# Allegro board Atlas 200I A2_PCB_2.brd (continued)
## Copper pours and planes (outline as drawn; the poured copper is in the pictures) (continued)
V_STBY_3V3 on TOP (solid shape): 21.39,117.73 21.39,117.02 21.31,116.94 20.32,116.94 20.19,117.07 20.19,117.22 21.16,117.22 21.16,117.58 20.73,117.58 20.73,117.22 20.19,117.22 20.19,117.6 20.37,117.78 21.34,117.78
V_STBY_3V3 on TOP (solid shape): 155.58,63.22 155.58,62.88 155.4,62.88 155.4,62.15 154.94,61.7 154.28,61.7 154.18,61.8 154.18,61.98 154.86,61.98 154.86,62.38 154.46,62.38 154.46,61.98 154.18,61.98 154.18,62.59 155.07,63.47 155.32,63.47
V_STBY_3V3 on TOP (solid shape): 59.51,33.48 59.51,30.3 59.21,30 59.21,28.47 58.8,28.07 57.15,28.07 57.02,28.19 57.02,28.32 57.28,28.32 57.28,28.96 58.67,30.35 58.67,30.78 59.28,30.78 59.28,31.65 58.98,31.65 58.98,30.78 58.67,30.78 58.67,33.48 58.8,33.6 59.39,33.6
V_STBY_3V3 on TOP (solid shape): 164.26,45.97 164.26,44.42 164.21,44.37 162.66,44.37 162.64,44.4 162.64,44.6 164.14,44.6 164.14,45.03 163.91,45.03 163.91,44.6 163.12,44.6 163.12,45.03 162.89,45.03 162.89,44.6 162.64,44.6 162.64,45.59 162.76,45.72 163.47,45.72 163.55,45.8 163.55,46.43 163.8,46.43
V_STBY_3V3 on TOP (solid shape): 186.79,160.15 186.79,157.96 186.51,157.68 184.96,157.68 184.79,157.86 184.79,158.8 185.6,158.8 185.6,159.13 185.14,159.13 185.14,158.8 184.79,158.8 184.79,159.77 185.6,159.77 185.6,160.07 185.19,160.07 185.19,159.77 184.79,159.77 184.79,160.15 184.91,160.27 186.66,160.27
V_STBY_3V3 on TOP (solid shape): 164.67,35.94 164.67,35.33 164.64,35.31 162.13,35.31 162.05,35.38 162.05,35.41 164.52,35.41 164.52,35.81 163.3,35.81 163.3,35.41 162.05,35.41 162.05,35.58 162.48,35.58 162.48,36.04 162.23,36.04 162.23,35.58 162.05,35.58 162.05,36.27 162.2,36.42 163.09,36.42 163.2,36.52 163.2,37.16 163.45,37.16
V_STBY_3V3 on TOP (solid shape): 198.15,62.26 198.17,61.79 198.25,61.34 198.25,59.28 198.07,59.11 198.07,58.6 197.92,58.45 197.66,58.45 197.66,58.67 196.98,58.67 196.98,58.52 197.03,58.52 197.03,58.39 196.8,58.39 196.77,58.42 196.77,58.83 196.88,58.93 197.16,58.93 197.59,59.36 197.59,70.18 198.15,70.18
V_STBY_3V3 on TOP (solid shape): 87,147.24 86.97,147.22 86.64,147.22 86.36,146.94 86.11,146.94 85.98,147.07 85.98,147.45 86.79,147.45 86.79,147.73 86.44,147.73 86.44,147.45 85.98,147.45 85.98,147.73 85.73,147.98 85.22,147.98 85.17,148.03 85.17,148.23 85.24,148.31 86.77,148.31 86.77,148.61 86.44,148.61 86.44,148.31 85.24,148.31 85.7,148.77 87,148.77
V_STBY_3V3 on TOP (solid shape): 203.63,26.76 203.63,25.22 203.53,25.12 202.69,25.12 202.55,25.26 202.53,25.28 202.49,25.31 202.43,25.33 202.43,25.35 203.38,25.35 203.38,25.63 202.97,25.63 202.97,25.35 202.43,25.35 202.43,25.55 202.36,25.55 202.26,25.65 200.58,25.65 200.48,25.76 200.48,26.29 203.35,26.29 203.35,26.57 202.92,26.57 202.92,26.29 200.48,26.29 200.48,26.49 200.54,26.55 202.12,26.55 202.13,26.54 202.46,26.54 202.7,26.79 203.6,26.79
V_STBY_3V3 on TOP (solid shape): 134.91,14.25 134.91,11.56 134.38,11.03 134.38,8.54 134.22,8.38 134.22,7.65 133.84,7.27 132.9,7.27 132.75,7.42 132.75,7.93 132.52,8.16 132.12,8.16 131.94,8.33 131.94,8.36 132.75,8.36 132.75,8.69 132.24,8.69 132.24,8.36 131.94,8.36 131.94,9.76 132.62,10.44 134.15,10.44 134.15,10.75 133.64,10.75 133.64,10.44 132.62,10.44 133.72,11.53 134.02,11.53 134.38,11.89 134.38,13.44 134.02,13.79 132.85,13.79 132.75,13.9 132.75,14.58 133.01,14.84 134.33,14.84
V_STBY_3V3 on TOP (solid shape): 158.25,60.06 158.25,59.45 158.29,59.41 158.29,58.19 158.57,57.91 158.57,57.2 158.47,57.1 158.24,57.1 158.24,57.91 157.99,57.91 157.99,57.1 157.61,57.1 157.61,58.04 157.23,58.04 157.23,57.1 156.95,57.1 156.79,57.25 156.79,58.27 158.04,58.27 158.04,58.7 157.76,58.7 157.76,58.27 156.79,58.27 156.79,58.39 156.67,58.52 157.45,58.52 157.45,58.83 157,58.83 157,58.52 156.67,58.52 156.62,58.57 156.62,58.98 156.9,59.26 157.01,59.26 157.1,59.35 157.1,59.63 157.66,60.2 158.12,60.2
V_STBY_3V3 on TOP (solid shape): 24.59,53.59 24.59,53.01 24.97,52.63 24.97,52.02 24.94,51.99 24.74,51.99 24.64,51.89 24.59,51.89 24.59,51.84 24.51,51.76 24.51,51.54 24.49,51.51 23.8,51.51 23.75,51.46 23.75,51.31 23.83,51.23 24.49,51.23 24.51,51.21 24.51,51.03 24.49,51 23.7,51 23.44,51.26 23.44,52.43 23.29,52.58 19.05,52.58 18.73,52.26 18.73,51.75 17.02,50.04 15.37,50.04 15.11,50.29 15.11,51.69 15.37,51.94 17.53,51.94 17.65,52.07 17.65,52.96 17.78,53.09 24.26,53.09 24.26,53.52 23.75,53.52 23.75,53.09 17.78,53.09 18.42,53.72 18.52,53.72 18.54,53.75 24.44,53.75
V_STBY_3V3 on TOP (solid shape): 82.45,165.3 82.45,163.85 82.58,163.73 82.58,162.53 82.45,162.41 81.74,162.41 81.53,162.2 81.53,161.8 80.87,161.14 80.62,161.14 80.26,160.78 80.26,159.13 80.26,159.13 79.63,159.13 79.63,159.13 79.63,160.91 80.39,161.67 80.39,161.72 81.03,161.72 81.03,161.98 80.62,161.98 80.62,161.72 80.39,161.72 80.39,162.56 82.19,162.56 82.19,162.79 81.84,162.79 81.84,162.56 80.39,162.56 80.39,162.61 81.03,162.61 81.03,162.89 80.57,162.89 80.57,162.61 80.39,162.61 80.39,162.94 80.37,162.94 80.01,163.3 80.01,163.42 82.35,163.42 82.35,163.65 81.97,163.65 81.97,163.42 80.01,163.42 80.01,164.59 80.95,165.53 82.22,165.53
V_STBY_3V3 on TOP (solid shape): 165.07,69.29 165.07,69.29 166.46,69.29 166.64,69.11 166.64,68.2 166.21,67.77 166.21,66.55 166.16,66.5 165.86,66.5 165.86,67.31 165.61,67.31 165.61,67.18 165.48,67.18 165.48,67.18 165.26,67.18 165.26,67.03 165.56,67.03 165.56,67.06 165.61,67.06 165.61,66.31 165.27,65.97 165.27,65.97 165.14,65.84 165.14,65.43 164.31,65.43 164.31,65.07 165.14,65.07 165.14,64.8 164.2,64.8 163.77,65.23 163.77,65.76 163.47,66.07 158.31,66.07 158.3,66.08 164.61,66.08 164.61,66.38 164.46,66.38 164.46,66.08 158.3,66.08 157.73,66.64 157.73,68.55 166.5,68.55 166.5,68.96 166.19,68.96 166.19,68.55 165.61,68.55 165.61,68.96 165.35,68.96 165.35,68.55 157.73,68.55 157.73,69.21 157.94,69.42 164.94,69.42
V_STBY_3V3 on TOP (solid shape): 121.18,27.71 121.18,27.23 121.11,27.15 118.75,27.15 118.52,27.38 119.89,27.38 119.89,27.76 119.46,27.76 119.46,27.38 118.52,27.38 118.49,27.41 117.86,27.41 115.27,24.82 114.35,24.82 113.34,23.8 113.13,23.8 113.13,19.63 113.77,19 115.14,19 115.85,18.29 115.85,16.33 115.72,16.2 112.45,16.2 111.68,16.97 111.68,23.9 111.94,24.15 111.94,26.59 113.64,28.3 115.28,28.3 115.29,28.29 115.32,28.29 115.34,28.27 115.36,28.25 115.37,28.22 115.38,28.2 115.38,28.17 115.36,28.13 115.35,28.08 115.34,28.03 115.34,27.97 115.35,27.92 115.36,27.87 115.38,27.82 115.41,27.77 115.45,27.73 115.49,27.7 115.54,27.67 115.59,27.64 115.64,27.63 115.69,27.62 115.75,27.62 115.8,27.63 115.85,27.64 115.9,27.67 115.95,27.7 115.99,27.73 116.03,27.77 116.06,27.82 116.08,27.87 116.08,27.89 120.29,27.89 120.29,28.19 119.74,28.19 119.74,27.89 116.08,27.89 116.09,27.92 116.1,27.97 116.1,28.03 116.09,28.09 116.08,28.14 116.05,28.19 116.03,28.23 116.03,28.3 116.08,28.3 116.1,28.32 119.79,28.32 119.88,28.42 120.47,28.42
V_STBY_3V3 on TOP (solid shape): outline of 134 points within 66.8,147.95 79.12,163.3
V_STBY_3V3 on TOP (solid shape): outline of 191 points within 171.58,36.27 175.51,53.59
V_STBY_3V3 on BOTTOM (solid shape): outline of 106 points within 113.11,7.24 134.32,17.78
V_STBY_3V3 on BOTTOM (solid shape): 184.9,16.72 184.88,16.65 184.87,16.57 185,16.27 185.31,16.14 185.38,16.15 185.46,16.17 193.68,7.95 195.58,7.95 199.72,12.09 199.77,12.04 210.31,12.04 210.59,12.32 211.58,12.32 211.96,11.94 211.96,11.25 211.4,10.69 202.31,10.69 202.39,10.82 202.41,10.97 201.98,11.4 201.55,10.97 201.58,10.82 201.65,10.69 201.6,10.69 195.55,4.65 190.4,4.65 189.81,5.23 189.81,8.69 181.34,17.16 181.61,17.3 181.73,17.59 181.6,17.89 181.29,18.02 181.01,17.91 180.86,17.64 180.34,18.16 179.38,18.16 179.32,18.11 178.97,18.11 178.92,18.16 171.22,18.16 171.04,18.34 171.04,19.13 171.2,19.28 182.35,19.28
V_STBY_3V3 on BOTTOM (solid shape): outline of 562 points within 39.91,20.6 60.1,33.83
V_STBY_3V3 on BOTTOM (solid shape): outline of 709 points within 149.5,44.91 165.99,65.13
V_STBY_3V3 on BOTTOM (solid shape): outline of 1075 points within 26.09,159.36 82.7,169.8
V_STBY_3V3 on ART03 (solid shape): outline of 148 points within 163.7,26.77 180.05,32.77
V_STBY_3V3 on ART03 (solid shape): outline of 188 points within 69.09,152.15 90.3,154.69
V_STBY_3V3 on ART03 (solid shape): outline of 935 points within 19.15,136.95 38.18,161.26
V_STBY_3V3 on ART04 (solid shape): 21.08,117.5 21.08,116.81 21.01,116.74 20.2,116.74 20,116.53 19.56,116.53 18.44,115.42 16.69,115.42 16.51,115.59 16.51,116.46 17.92,117.87 20.71,117.87
V_STBY_3V3 on ART04 (solid shape): outline of 300 points within 39.49,19.66 46.99,28.83
V_STBY_3V3 on ART04 (solid shape): outline of 347 points within 8.76,137.16 21.46,146.18
V_STBY_3V3 on ART04 (solid shape): outline of 567 points within 191.01,20.86 208.41,43.43
V_STBY_3V3 on ART04 (solid shape): outline of 932 points within 80.7,164.85 117.53,192.99
V_STBY_3V3 on TOP: 16.03,116.23 17.98,116.23 18.14,116.08 18.14,115.37 16.79,114.02 15.16,114.02 13.84,112.7 10.24,112.7 9.63,112.09 4.75,112.09 4.62,112.22 4.62,115.49 4.75,115.62 5.39,115.62 5.49,115.52 5.49,114.88 5.82,114.55 5.82,114.1 6.78,113.13 9.07,113.13 9.5,113.56 9.5,115.32 9.63,115.44 10.08,115.44 10.26,115.26 10.26,114.3 10.8,113.77 12.88,113.77 13.61,114.5 14.12,114.5 14.61,114.99 15.7,114.99 15.93,115.21 15.93,116.13 ; 4 cut-outs
V_STBY_3V3 on TOP: 40.64,20.7 40.64,22.86 40.77,22.99 41.53,22.99 41.66,22.86 41.66,22.2 41.53,22.07 41.53,21.18 41.66,21.06 41.66,20.7 41.53,20.57 40.77,20.57 ; 1 cut-out
V_STBY_3V3 on TOP: 8.38,139.12 9.7,139.12 9.98,138.84 9.98,138.07 9.83,137.92 8.51,137.92 8.18,138.25 8.18,138.91 ; 1 cut-out
V_STBY_3V3 on TOP: 20.37,137.34 21.39,137.34 21.51,137.46 21.51,138.68 21.39,138.81 19.79,138.81 19.74,138.76 19.74,138.38 20.24,137.87 20.24,137.46 ; 2 cut-outs
V_STBY_3V3 on TOP: 204.98,30.68 205.54,30.68 205.59,30.63 205.59,28.8 205.92,28.47 206.12,28.47 206.53,28.07 206.53,25.83 206.38,25.68 205.54,25.68 205.33,25.88 205.33,27.08 204.7,27.71 204.7,28.12 204.67,28.14 204.67,28.5 204.5,28.68 201.96,28.68 201.3,28.02 200.58,28.02 200.41,28.19 200.41,29.26 201.07,29.92 202.06,29.92 202.74,30.61 204.9,30.61 ; 3 cut-outs
V_STBY_3V3 on TOP: 32.64,161.8 36.32,161.8 36.86,161.26 36.86,160.38 36.65,160.17 35.59,160.17 35.43,160.32 35.43,160.58 34.98,161.04 32.64,161.04 32.51,161.16 32.51,161.67 ; 2 cut-outs
V_STBY_3V3 on BOTTOM: 122.43,175.28 122.43,185.57 118.69,189.31 115.65,189.31 115.21,188.87 115.21,187.6 115.75,187.07 118.06,187.07 119.15,185.98 119.15,174.55 119.13,174.52 119.13,172.36 120.47,171.02 137.64,171.02 139.7,168.96 185.47,168.96 188.95,172.44 188.95,172.92 190.88,174.85 194.92,174.85 198.17,171.6 198.17,168.93 201.02,166.09 202.16,166.09 202.46,166.39 202.46,167.69 200.84,169.32 200.84,174.5 198.09,177.24 187.45,177.24 182.75,172.54 139.5,172.54 138.25,173.79 123.93,173.79
V_STBY_3V3 on BOTTOM: 86.36,153.67 89.79,153.67 89.92,153.54 89.92,152.65 88.34,151.08 88.34,150.17 86.87,148.7 86.87,147.12 86.46,146.71 85.75,146.71 85.32,147.14 85.32,149.96 86.11,150.75 86.11,153.42
V_STBY_3V3 on BOTTOM: outline of 312 points within 185.55,38.97 213.87,52.41
V_STBY_3V3 on ART03: 185.29,41.22 187.96,41.22 187.96,39.6 182.06,39.6 181.31,40.35 181.31,40.77 181.74,41.2 185.27,41.2
V_STBY_3V3 on ART03: 148.78,63.02 150,63.02 150.38,62.64 150.38,61.51 149.91,61.05 142.16,61.05 141.01,62.21 141.01,62.61 143.31,62.61 143.31,62.43 148.2,62.43
V_STBY_3V3 on ART03: outline of 131 points within 4.24,3.7 176.48,139.83
V_STBY_3V3 on ART03: 155.32,69.75 157.99,69.75 158.55,69.19 158.55,59.38 158.24,59.08 157.15,59.08 157.02,59.21 157.02,59.71 154.36,62.38 154.36,68.78
V_STBY_3V3 on ART04: 120.7,27.61 121.08,27.61 121.72,26.97 126.44,26.97 126.44,26.19 127.33,26.19 127.33,25.98 127.97,25.98 128.12,25.83 128.12,25.48 127.51,24.87 127.51,24.13 126.11,24.13 126.06,24.18 126.06,24.61 126.01,24.61 125.02,25.6 121.54,25.6 120.93,26.21 120.93,26.31 120.32,26.92 120.32,27.23
V_STBY_3V3 on ART04: 165.66,38.35 164.52,39.5 164.52,45.9 164.31,46.1 162.76,46.1 162.43,45.77 162.43,36.25 161.06,34.87 161.06,26.8 169.55,18.31 171.12,18.31 171.12,18.29 176,18.29 176.23,18.52 176.23,19.48 175.46,20.24 172.75,20.24 172.58,20.41 172.58,23.08 170.59,25.07 170.59,25.55 166.7,29.44 166.7,30.56 165.66,31.6
V_STBY_3V3 on ART04: 178.68,40.88 182.16,40.88 182.85,40.2 182.85,35.27 179.72,32.15 178.67,32.15 178.56,32.26 178.44,32.13 173.91,32.13 173.91,35.05 173.2,35.05 172.39,35.86 172.39,38.2 172.54,38.35 172.54,38.68 174.3,40.44 177.29,40.44 177.52,40.21 178,40.21
V_STBY_5V0 on TOP (solid shape): 238,179.25 238,178.13 237.69,177.82 236.93,177.82 236.91,177.8 236.35,177.8 236.09,177.55 236.09,176.78 234.57,176.78 234.32,177.04 234.32,178.94 234.57,179.2 235.41,179.2 235.59,179.37 237.87,179.37
V_STBY_5V0 on TOP (solid shape): 155.41,60.67 155.41,59.85 155.7,59.56 155.7,58.42 155.58,58.29 155.24,58.29 155.24,58.32 154.66,58.32 154.18,58.8 154.18,60.58 154.66,60.58 154.66,60.96 154.43,60.96 154.43,60.58 154.18,60.58 154.18,61.21 154.2,61.24 154.84,61.24
V_STBY_5V0 on TOP (solid shape): 138.18,24.87 139.07,24.87 139.12,24.82 139.12,23.82 138.91,23.62 138.49,23.62 138.42,23.64 138.35,23.65 138.1,23.55 137.98,23.32 137.87,23.22 136.04,23.22 135.48,23.77 135.48,25.12 135.5,25.13 137.91,25.13
V_STBY_5V0 on TOP (solid shape): 98.27,158.06 98.27,154.1 97.03,152.86 97.03,149.1 96.34,148.41 96.34,145.52 95.86,145.03 94.21,145.03 94.01,145.24 94.01,145.41 94.77,145.41 94.77,145.69 94.21,145.69 94.21,145.41 94.01,145.41 94.01,146.28 94.77,146.28 94.77,146.58 94.29,146.58 94.29,146.28 94.01,146.28 94.01,147.6 94.21,147.8 94.21,153.49 95.25,154.53 95.25,158.19 95.48,158.42 97.92,158.42
V_STBY_5V0 on TOP (solid shape): 151.41,30.63 151.41,30.48 151.59,30.3 152.22,30.3 152.22,30.02 152.12,29.92 151.59,29.92 150.72,29.06 150.72,28.57 150.27,28.12 150.27,27.01 150.24,26.99 150.19,26.95 150.15,26.91 150.12,26.85 150.09,26.8 150.07,26.74 150.06,26.68 150.06,26.62 150.07,26.57 150.08,26.52 150.09,26.49 150.07,26.47 150.02,26.43 149.99,26.37 149.96,26.32 149.95,26.26 149.94,26.19 149.94,26.14 149.94,26.08 149.95,26.03 149.96,26.01 149.86,25.91 148.08,25.91 147.96,26.03 147.96,29.97 150.88,29.97 150.88,30.61 150.5,30.61 150.5,29.97 147.96,29.97 147.96,30.58 148.29,30.91 151.13,30.91
V_STBY_5V0 on TOP (solid shape): 187.05,38.43 187.05,36.63 186.36,35.94 186.36,35.48 186.06,35.18 185.42,35.18 185.42,35.13 184.2,35.13 183.39,35.94 184.02,35.94 184.03,35.88 184.04,35.83 184.06,35.78 184.09,35.73 184.12,35.69 184.16,35.65 184.21,35.61 184.25,35.59 184.31,35.57 184.36,35.56 184.42,35.56 184.47,35.56 184.53,35.58 184.58,35.6 184.63,35.63 184.67,35.67 184.71,35.71 184.74,35.75 184.76,35.8 184.78,35.86 184.79,35.91 184.79,35.97 184.78,36.02 184.76,36.08 184.74,36.13 184.71,36.17 184.67,36.22 184.63,36.25 184.58,36.28 184.53,36.3 184.47,36.32 184.42,36.32 184.36,36.32 184.31,36.31 184.25,36.29 184.21,36.27 184.16,36.23 184.12,36.2 184.09,36.15 184.06,36.1 184.04,36.05 184.03,36 184.02,35.94 183.39,35.94 183.34,35.99 183.34,37.97 184.02,38.66 186.82,38.66
V_STBY_5V0 on BOTTOM (solid shape): 34.49,168.27 34.54,168.27 34.8,168.02 34.8,167.89 34.82,167.87 46.08,167.87 46.46,167.49 46.46,166.25 46.46,166.25 46.46,164.87 46.13,164.54 42.24,164.54 40.14,166.65 34,166.65 33.07,167.58 32.48,168.17 32.48,168.66 32.82,168.99 33.78,168.99
V_STBY_5V0 on BOTTOM (solid shape): outline of 196 points within 28.8,23.37 77.6,51.68
V_STBY_5V0 on BOTTOM (solid shape): outline of 372 points within 94.11,145.92 98.79,173.14
V_STBY_5V0 on ART03 (solid shape): outline of 4971 points within 10.24,49.25 34.82,170.97
V_STBY_5V0 on TOP: 192.38,24.76 192.38,23.49 192.61,23.27 194.08,23.27 194.59,23.77 194.59,24.54 194.41,24.71 193.93,24.71 193.65,24.99 193.65,25.65 193.45,25.86 191.77,25.86 191.72,25.81 191.72,25.3 191.77,25.25 191.9,25.25 ; 1 cut-out
V_STBY_5V0 on TOP: 105.18,192.18 104.52,191.52 104.52,187.96 104.78,187.71 105.92,187.71 106.55,188.34 106.55,192 106.38,192.18
V_STBY_5V0 on TOP: 126.24,191.77 124.71,191.77 124.08,191.13 124.08,189.23 124.84,188.47 126.11,188.47 126.37,188.72 126.37,191.64
V_STBY_5V0 on ART03: outline of 179 points within 43.08,163.7 235.71,190.94
V_STBY_5V0 on ART03: 183.54,36.55 186.61,36.55 186.7,36.46 187.06,36.46 187.96,35.56 187.96,33.45 188.6,32.82 190.88,32.82 191.29,32.41 191.29,30.78 190.96,30.45 184.63,30.45 184.56,30.53 183.41,30.53 181.25,32.69 170.92,32.69 170.61,32.38 170.61,31.83 169.72,30.94 166.52,30.94 155.52,19.94 136.45,19.94 135.38,21.01 135.38,22.81 136.32,23.75 145.49,23.75 148.21,26.47 157.71,26.47 165.79,34.54 171.15,34.54 172.03,35.43 176.53,35.43 176.78,35.18 181.48,35.18 182.75,36.45 182.75,36.55 183.54,36.55
V_STBY_5V0 on ART04: 155.14,59.56 156.72,59.56 157.91,58.37 157.91,54.51 158.75,53.67 158.75,51.21 159.7,50.25 159.7,29.45 155.45,25.2 148.06,25.2 147.83,25.42 147.83,27.15 147.98,27.3 147.98,28.68 148.54,29.23 149.73,29.23 150.39,29.9 156.13,29.9 156.85,30.61 156.85,32.64 156.39,33.1 156.39,42.47 154.97,43.89 154.97,45.57 155.04,45.64 155.04,50.06 154.51,50.6 154.51,58.93 ; 3 cut-outs
V_STBY_5V0 on ART04: 189.74,27.3 189.74,30.86 190.32,31.44 191.03,31.44 191.24,31.24 191.24,28.9 193.47,26.67 193.47,25.2 193.29,25.02 192.02,25.02
V_STBY_5V0 on ART04: 128.3,25.09 136.88,25.25 138.02,24.1 138.02,23.19 137.72,22.88 134.32,22.88 134.32,22.81 132.56,21.06 128.91,21.06 128.09,21.87 79.88,21.87 79.6,22.15 79.12,22.15 78.87,22.4 77.34,22.4 76.45,23.29 76.45,24.97 76.73,25.25 124.92,25.2 125.37,24.79 125.5,24.66 125.7,24.36 127.66,24.36 127.86,24.64 128.02,24.79
V_STBY_12V0 on TOP (solid shape): 188.04,73.23 188.04,71.55 187.71,71.22 186.08,71.22 185.93,71.37 185.93,73.51 186.06,73.63 187.64,73.63
V_STBY_12V0 on TOP (solid shape): 33.25,156.46 33.25,152.79 29.92,152.79 29.79,152.92 29.79,156.54 29.95,156.69 33.02,156.69
V_STBY_12V0 on TOP (solid shape): 105.21,183.41 105.21,181.46 104.98,181.23 104.37,181.23 104.09,180.95 104.09,180.48 104.01,180.41 104.01,179.3 103.84,179.12 103.81,179.12 103.71,179.02 103.71,178.49 103.45,178.49 103.45,178.23 103.71,178.23 103.71,178.08 103.61,177.98 103.61,177.11 103.58,177.09 103.2,177.09 103.07,177.22 103.07,177.77 102.93,177.91 102.93,178.62 102.18,179.37 101.07,179.37 101.07,183.24 101.32,183.49 105.13,183.49
V_STBY_12V0 on TOP (solid shape): 102.41,169.75 102.41,167.59 102.11,167.28 102.11,165.73 102.18,165.66 102.18,164.79 102.29,164.69 102.29,163.88 102.26,163.85 102.06,163.85 102.06,164.49 101.75,164.49 101.75,163.85 101.57,163.85 101.57,164.52 101.27,164.52 101.27,163.85 100.78,163.85 100.78,163.86 100.33,163.86 100.17,164.02 100.17,165.02 100.15,165.03 100.15,165.07 101.85,165.07 101.85,165.35 101.42,165.35 101.42,165.07 100.15,165.07 100.15,165.38 99.92,165.61 99.92,167.31 99.29,167.94 98.48,167.94 98.22,168.2 98.22,169.72 98.65,170.15 102.01,170.15
V_STBY_12V0 on TOP (solid shape): 168.73,63.63 167.16,63.63 166.22,62.48 166.22,60.75 166.22,59.5 166.65,59.07 166.65,58.28 166.68,58.25 166.68,57.99 166.85,57.81 166.85,57.76 167.39,57.76 167.41,57.78 169.49,57.78 169.49,57.75 169.7,57.75 169.93,57.53 169.93,56.31 169.6,55.98 166.37,55.98 165.28,57.07 159.82,57.07 159.54,57.35 159.54,57.61 159.57,57.65 159.6,57.71 159.63,57.78 159.65,57.85 159.66,57.92 159.67,58 159.66,58.07 159.65,58.14 159.63,58.21 159.6,58.28 159.56,58.34 159.54,58.37 159.54,58.62 166.47,58.62 166.47,58.9 165.99,58.9 165.99,58.62 159.54,58.62 159.54,60.32 159.82,60.6 162.73,60.6 163.6,61.47 163.6,62.73 164.05,62.73 164.05,61.27 164.15,61.27 164.15,60.39 164.46,60.08 164.46,60.07 165.01,60.07 165.01,59.97 165.82,59.97 165.82,60.11 165.91,60.2 165.91,62.48 165.56,62.82 164.29,62.82 164.2,62.73 163.6,62.73 163.6,62.95 163.8,63.14 165.14,63.14 165.14,63.13 166.22,63.13 167.16,63.94 168.73,63.94
V_STBY_12V0 on ART03 (solid shape): 213.28,24.26 213.26,24.23 213.26,22.63 212.73,22.1 209.78,22.1 209.78,22.14 209.3,22.56 208.82,22.14 208.81,22.1 208.05,22.1 208.05,22.14 207.89,22.44 207.57,22.56 207.25,22.44 207.09,22.14 207.08,22.1 204.8,22.1 202.65,19.94 200.79,19.94 200.66,20.07 200.66,20.29 200.96,20.6 200.98,20.6 201.31,20.74 201.45,21.06 201.45,21.08 203.73,23.37 204.47,23.37 204.49,23.33 204.66,23.11 204.94,23.02 205.21,23.11 205.39,23.33 205.4,23.37 207.66,23.37 207.84,23.15 208.1,23.07 208.37,23.15 208.55,23.37 208.85,23.37 209.3,23.07 209.74,23.37 210.19,23.37 211.33,24.51 213.03,24.51
V_STBY_12V0 on ART03 (solid shape): outline of 716 points within 99.47,151.94 174.3,179.65
V_STBY_12V0 on ART04 (solid shape): outline of 180 points within 102.54,176.05 111.88,183.13
V_STBY_12V0 on ART04 (solid shape): outline of 1200 points within 38.38,157.48 101.27,169.8
V_STBY_12V0 on TOP: 208.56,27.46 212.78,27.46 213.21,27.03 213.21,24.05 213.13,23.98 208.48,23.98 208.38,24.08 208.38,27.28
V_STBY_12V0 on TOP: 18.12,162.56 20.83,162.56 21.08,162.31 21.08,160.4 20.83,160.15 18.22,160.15 17.89,160.48 17.89,162.33
V_STBY_12V0 on TOP: 32.89,145.92 30.23,145.92 29.21,146.94 28.32,146.94 28.07,146.68 28.07,143.51 28.19,143.38 33.02,143.38 33.15,143.51 33.15,145.67
V_STBY_12V0 on BOTTOM: 192.43,71.93 194.44,73.94 194.44,117.7 178.79,133.35 178.79,150.57 176.05,153.31 170.64,153.31 168.96,151.64 168.5,151.64 167.69,150.82 167.69,125.25 185.24,107.7 185.24,80.9 184.53,80.19 184.53,73.82 186.42,71.93
V_STBY_12V0 on BOTTOM: outline of 106 points within 3.43,5.46 77.22,161.9 ; 3 cut-outs
V_STBY_12V0 on ART03: 26.62,156.92 26.62,154.48 27.43,153.67 30.23,153.67 30.61,154.05 30.86,154.05 31.06,154.25 31.06,161.24 33.15,163.32 39.4,163.32 40.89,164.82 40.89,166.75 39.88,167.77 34.82,167.77 34.19,167.13 30.73,167.13 27.31,163.7 27.31,157.61
V_STBY_12V0 on ART04: 161.85,56.9 167.31,56.9 167.35,56.93 168.44,56.93 173.79,62.28 178.46,62.28 187.45,71.27 187.45,73.53 186.56,74.42 185.04,74.42 178.28,67.67 171.15,67.67 164.16,60.68 161.44,60.68 160.83,60.07 160.83,57.91
V_STBY_12V0 on ART04: 29.49,143.31 32.79,143.31 33.05,143.56 33.05,156.82 32.79,157.07 27.58,157.07 27.33,156.82 27.33,145.49 29.49,143.33
V_STBY_12V0 on ART04: 211.2,24.51 213.36,24.51 214.45,23.42 214.45,15.9 206.86,8.31 196.11,8.31 196.88,8.79 197.18,9.65 195.8,11.03 194.42,9.65 194.72,8.79 195.49,8.31 194.03,8.31 190.63,4.9 190.63,4.8 174.27,4.8 169.8,9.27 166.5,9.27 163.5,6.27 148.29,6.27 147.75,6.81 142.67,6.81 142.44,6.58 92.51,6.58 92.2,6.27 88.6,6.27 88.16,6.71 75.92,6.71 75.18,7.44 75.18,9.4 76.48,10.69 141.43,10.69 144.48,13.74 154.31,13.74 154.31,11.3 161.16,11.3 161.16,13.74 172.31,13.74 178.05,8 187.27,8 193.01,13.74 193.03,13.73 193.6,14.3 205.51,14.3 208.32,17.11 209.77,17.11 211.84,19.18 211.84,19.76 210.9,20.7 210.9,24.21
V_STBY_TEC_12V0 on TOP (solid shape): outline of 94 points within 175.74,63.32 187.71,71.58
V_TPM_3V3 on TOP (solid shape): outline of 162 points within 43.54,25.6 59.69,32.92
V_TPM_3V3 on TOP (solid shape): outline of 214 points within 40.22,25.6 59.69,33.23
V_VCC_1V8_EMMC on TOP (solid shape): 35.41,160.47 35.41,157.91 34.8,157.3 34.8,157.23 34.67,157.1 29.34,157.1 29.25,157.19 28.96,157.19 28.94,157.21 28.94,157.5 29.3,157.86 29.97,157.86 29.98,157.85 31.68,157.85 31.8,157.73 33.5,157.73 33.83,158.07 33.83,160.62 33.95,160.74 35.14,160.74
V_VCC_1V8_EMMC on TOP (solid shape): outline of 303 points within 46.48,139.79 60.12,159.77
V_VCC_1V8_EMMC on BOTTOM: 49.13,157.51 49.13,156.79 48.73,156.39 42.11,156.39 40.13,158.37 39.37,158.37 38.75,157.75 35.7,157.75 33.86,159.59 33.86,160.52 34.34,161 40.32,161 42.29,159.03 47.61,159.03
V_VCC_3V3 on TOP (solid shape): 157.35,68.53 157.35,67.51 157.3,67.46 157.35,67.41 157.35,67.33 157.18,67.16 154.69,67.16 154.48,67.36 154.48,67.49 155.04,67.49 155.04,67.94 154.66,67.94 154.66,67.49 154.48,67.49 154.48,68.12 154.51,68.15 155.52,68.15 156.07,68.69 157.19,68.69
V_VCC_3V3 on TOP (solid shape): 109.8,153.67 109.8,152.32 110.03,152.09 110.03,151.38 109.91,151.26 109.12,151.26 108.89,151.49 108.89,151.54 109.8,151.54 109.8,151.89 109.42,151.89 109.42,151.54 108.89,151.54 108.89,152.17 109.09,152.37 109.09,153.01 109.65,153.01 109.65,153.47 109.25,153.47 109.25,153.01 109.09,153.01 109.09,153.62 109.19,153.71 109.76,153.71
V_VCC_3V3 on TOP (solid shape): 158.72,56.57 158.72,53.72 158.6,53.59 157.15,53.59 157.12,53.6 157.07,53.61 157.02,53.62 156.97,53.62 156.92,53.61 156.87,53.6 156.85,53.59 155.6,53.59 155.52,53.52 153.95,53.52 153.85,53.62 153.85,54.99 155.32,54.99 155.32,55.45 154.83,55.45 154.83,54.99 153.85,54.99 153.85,55.17 154.36,55.68 154.53,55.68 154.56,55.7 155.83,55.7 156.13,56.01 156.13,56.57 156.29,56.72 158.57,56.72
V_VCC_3V3 on TOP (solid shape): 100.46,149.38 100.46,144.17 100.2,143.92 97.26,143.92 96.77,144.4 98.88,144.4 98.88,144.86 98.55,144.86 98.55,144.4 96.77,144.4 96.75,144.42 96.75,145.82 96.95,146.02 97.99,146.02 98.17,145.85 98.17,145.19 98.25,145.11 99.26,145.11 99.52,145.36 99.52,147.29 100.3,147.29 100.3,147.65 100.05,147.65 100.05,147.29 99.52,147.29 99.52,147.37 99.73,147.59 99.73,147.92 100.15,148.34 100.15,148.77 100.2,148.82 100.2,149.4 100.25,149.45 100.38,149.45
V_VCC_3V3 on BOTTOM (solid shape): outline of 213 points within 18.42,140.84 34.29,148.08
V_VCC_3V3 on ART03 (solid shape): outline of 134 points within 96.88,145.5 109.55,152.37
V_VCC_3V3 on ART03 (solid shape): outline of 5071 points within 26.92,29.84 154.66,149.06
V_VCC_3V3 on ART04 (solid shape): outline of 1198 points within 54.89,143.31 109.12,154.2
V_VCC_3V3 on TOP: 25.65,146.91 26.16,146.91 27,146.07 27,145.97 27.05,145.92 27.05,144.27 26.92,144.14 24,144.14 23.52,143.66 23.52,143.28 18.42,143.28 17.98,143.71 13.11,143.71 12.92,143.9 10.96,143.9 10.77,143.71 8.31,143.71 8,144.02 8,145.06 7.62,145.44 7.62,146.86 7.67,146.91 7.87,146.91 7.87,145.54 8.13,145.54 8.13,146.91 8.41,146.91 8.46,146.86 8.46,145.49 8.61,145.34 10.03,145.34 10.13,145.44 10.13,146.89 10.41,146.89 10.41,145.41 10.67,145.41 10.67,146.89 10.92,146.89 10.92,145.41 11.18,145.41 11.18,146.89 11.43,146.89 11.43,145.41 11.56,145.41 11.56,146.89 11.71,146.89 11.89,146.71 11.89,145.49 12.09,145.29 24.38,145.29 24.59,145.49 24.59,146.84 24.66,146.91 24.89,146.91 24.89,145.41 25.15,145.41 25.15,146.91 25.4,146.91 25.4,145.41 25.65,145.41 ; 6 cut-outs
V_VCC_3V3 on BOTTOM: 41.91,153.06 41.91,146 42.29,145.62 44.5,145.62 45.9,147.01 45.9,151.59 47.07,152.76 53.75,152.76 53.76,152.77 56.1,152.77 56.82,153.49 56.82,155.27 56.16,155.93 49.63,155.93 49.12,155.42 44.27,155.42
V_VCC_3V3_EMMC on TOP: 37.59,163.83 38.35,163.83 38.48,163.7 38.48,161.04 39.24,160.27 39.24,157.61 41.53,155.32 41.53,150.39 40.18,150.39 40.18,154.25 38.74,155.7 38.74,156.34 37.97,157.1 37.97,160.27 36.96,161.29 36.96,163.19 ; 5 cut-outs
V_VCC_AUDIO_5V0 on TOP: 185.75,21.72 186.21,22.17 188.01,22.17 188.04,22.2 188.04,22.22 189.64,23.82 190.25,23.82 190.63,24.21 190.63,24.82 190.75,24.94 191.74,24.94 191.95,24.74 191.95,23.16 191.77,22.99 190.12,22.99 189.92,22.78 189.54,22.78 188.09,21.34 186.18,21.34 185.8,20.95 183.68,20.95 183.59,21.04 183.59,21.61 183.69,21.72 ; 2 cut-outs
V_VCC_DISK_5V0 on TOP (solid shape): outline of 90 points within 179.15,26.42 196.85,30.86
V_VCC_DISK_5V0 on ART03 (solid shape): outline of 225 points within 195.23,28.6 207.05,37.72
V_VCC_DISK_5V0 on TOP: 225.17,37.59 240.28,37.59 240.92,36.96 240.92,32.64 240.54,32.26 237.11,32.26 236.47,32.89 236.47,34.8 235.46,35.81 232.16,35.81 232.12,35.78 228.51,35.78 228.19,35.46 228.19,34.37 228.04,34.21 225.3,34.21 225.04,34.47 225.04,37.46
V_VCC_DISK_5V0 on BOTTOM: 225.92,40.4 228.22,38.1 239.14,38.1 240.41,36.83 240.41,33.4 239.9,32.89 237.87,32.89 237.36,33.4 237.36,35.43 236.35,36.45 230.76,36.45 228.85,34.54 224.08,34.54 223.37,35.25 217.65,35.25 216.09,37.36 213.6,38.17 211.11,37.36 209.55,35.25 206.57,35.25 205.57,36.25 205.57,37.01 205.61,37.01 205.61,37.46 205.74,37.59 206.38,37.59 206.96,37.01 207.79,37.01 210.2,39.42 211.84,39.42 212.82,40.4
V_VCC_DISK_12V0 on TOP: 222.89,37.97 224.03,37.97 224.16,37.85 224.16,34.16 224.54,33.78 231.14,33.78 232.79,35.43 234.19,35.43 235.08,34.54 235.08,32.64 234.12,31.69 224.75,31.69 224.41,31.34 224.41,29.84 223.14,28.57 223.14,21.84 222.76,21.46 219.96,21.46 219.84,21.59 219.84,22.35 219.71,22.48 218.82,22.48 218.41,22.88 218.41,27.13 218.59,27.3 220.47,27.3 221.01,27.84 221.01,28.35 222.36,29.7 222.36,37.45
V_VCC_DISK_12V0 on BOTTOM: 232.54,35.43 234.44,35.43 235.08,34.8 235.08,32.51 234.25,31.69 224.73,31.69 224.54,31.88 224.54,33.65 224.66,33.78 230.89,33.78
V_VCC_DISK_12V0 on ART03: 222.73,34.04 227.25,34.04 228.27,33.02 228.27,26.72 226.64,26.72 226.54,26.62 225.04,26.62 223.76,25.34 223.76,21.78 223.62,21.64 223.62,21.03 219.3,21.03 217.88,22.45 217.88,24.64 221.59,28.35 221.59,32.89
V_VCC_DISK_12V0 on ART04: 217.88,25.37 217.88,22.45 219.3,21.03 226.97,21.03 228.27,22.33 228.27,36.32 226.92,37.67 222.25,37.67 221.59,37.01 221.59,29.08
V_VCC_LED_3V3 on TOP (solid shape): 65.02,7.75 66.5,7.75 66.5,6.22 66.47,6.2 62.92,6.2 62.61,6.5 62.61,7.37 62.48,7.49 61.95,7.49 61.82,7.62 61.82,8.48 61.87,8.53 64.24,8.53
V_VDD_3V3_PHY0 on TOP (solid shape): 157.71,70.15 157.71,69.57 157.51,69.37 155.68,69.37 155.3,68.99 155.3,68.58 155.19,68.48 155.17,68.48 155.17,68.48 154.51,68.48 154.51,68.48 154.29,68.48 154.28,68.5 154.24,68.54 154.21,68.58 154.17,68.61 154.12,68.64 154.08,68.66 154.03,68.67 153.98,68.68 153.92,68.68 153.86,68.67 153.8,68.65 153.75,68.62 153.72,68.61 153.59,68.73 155.02,68.73 155.02,69.16 154.66,69.16 154.66,68.73 153.59,68.73 153.47,68.86 153.47,68.94 154.15,68.94 154.15,69.24 153.77,69.24 153.77,68.94 153.47,68.94 153.47,69.5 153.53,69.57 153.95,69.57 153.98,69.6 157.48,69.6 157.48,70 157.25,70 157.25,69.6 156.54,69.6 156.54,70 156.24,70 156.24,69.6 153.98,69.6 154,69.62 155.52,69.62 155.52,69.98 155.25,69.98 155.25,69.62 154,69.62 154.65,70.27 155.38,70.27 155.4,70.28 157.58,70.28
V_VDD_3V3_PHY0 on TOP: 139.01,64.26 139.04,64.29 139.07,64.26 143.28,64.26 143.41,64.13 143.41,63.7 143.33,63.63 142.49,63.63 142.24,63.37 142.24,62.99 142.11,62.86 140.34,62.86 140.21,62.74 138.46,62.74 138.33,62.86 138.3,62.86 138.3,64.21 138.35,64.26 ; 1 cut-out
V_VDD_3V3_PHY0 on ART03: 143.84,70.21 143.84,68.26 141.54,65.96 138.74,65.96 137.95,65.18 137.95,63.25 138.23,62.97 142.56,62.97 144.07,64.48 144.69,64.48 145.03,64.13 149.4,64.13 150.34,65.07 150.34,65.84 149.82,66.36 147.18,66.36 147.02,66.52 147.02,68.45 145.09,70.38 144.02,70.38
V_VDD_3V3_PHY0 on ART04: 155.27,67.82 154.36,66.9 152.55,66.9 150.6,64.95 149.73,64.95 149.4,65.28 149.4,65.71 151.54,67.84 152.07,67.84 152.5,68.27 152.55,68.27 154.31,70.03 154.84,70.03 155.28,69.58 155.27,69.57
XGND on TOP: 4.17,130.68 6.5,130.68 9.25,127.94 9.83,127.94 9.86,127.91 9.86,127.71 9.83,127.69 8.86,127.69 8.56,127.99 7.14,127.99 6.78,127.63 5.82,127.63 5.74,127.71 5.74,128.78 7.37,128.78 7.37,129.03 7.24,129.16 6.99,129.16 6.48,129.67 6.22,129.67 5.84,130.05 5.08,130.05 4.95,129.92 4.95,129.29 4.83,129.16 4.32,129.16 4.12,128.96 4.12,127.02 4.29,126.85 5.21,126.85 5.26,126.8 5.26,125.81 5.39,125.68 5.39,124.76 5.49,124.66 6.38,124.66 6.55,124.84 6.55,125.37 7.32,126.14 8.66,126.14 8.99,126.47 9.83,126.47 9.86,126.44 9.86,126.26 9.8,126.21 9.2,126.21 7.19,124.21 4.24,124.21 3.61,124.84 3.61,130.12 ; 2 cut-outs
$7N42483 on TOP (solid shape): 144.96,70.76 144.96,70.1 145.14,69.93 145.14,68.5 144.53,67.89 144.53,67.29 144.4,67 144.53,66.72 144.53,64.74 144.39,64.6 144.19,64.6 144.19,64.6 144.01,64.6 143.76,64.85 143.76,66.47 143.92,66.62 143.92,68.76 144.75,69.6 144.75,70.76 144.78,70.79 144.93,70.79
$8N44609 on TOP (solid shape): 124.06,160.24 124.06,160.16 124.16,160.07 124.16,159.46 124,159.31 123.7,159.31 123.27,159.74 122.83,159.74 122.71,159.87 122.71,160.6 122.81,160.71 123.6,160.71
$9N34276 on TOP: 32.26,163.35 32.26,162.28 32.49,162.05 34.09,162.05 35.06,163.03 35.62,163.03 35.74,163.14 35.74,163.6 35.59,163.75 34.24,163.75 34.06,163.58 32.49,163.58 ; 4 cut-outs
$13N103139 on TOP (solid shape): 155.22,30.73 155.22,29.84 154.98,29.6 153.79,29.6 153.7,29.69 153.7,30.23 153.75,30.28 154.25,30.28 154.48,30.5 154.91,30.5 154.91,30.78 155.17,30.78
$13N103146 on TOP (solid shape): 141.84,24.81 142.21,24.81 142.21,24.69 142.09,24.57 141.41,24.57 141.22,24.38 140.64,24.38 140.59,24.43 140.59,24.82 140.64,24.87 141.1,24.87 141.33,25.09 141.84,25.09
$13N120944 on TOP (solid shape): 236.14,175.23 236.14,174.6 235.81,174.27 233.76,174.27 233.71,174.32 233.71,174.62 233.99,174.62 233.99,175.28 236.09,175.28
$15N26586 on TOP: 98.17,191.77 99.95,191.77 100.46,192.28 101.6,192.28 101.73,192.15 101.73,189.23 101.47,188.98 100.46,188.98 99.06,190.37 98.17,190.37 98.04,190.5 98.04,191.64
$20N51834 on TOP (solid shape): 153.9,62.25 153.9,60.2 153.85,60.15 153.85,59.56 153.57,59.28 151.71,59.28 151.66,59.33 151.66,60.27 151.84,60.45 151.84,60.83 153.59,60.83 153.59,61.09 153.21,61.09 153.21,60.83 151.84,60.83 151.84,61.59 153.77,61.59 153.77,61.95 153.49,61.95 153.49,61.59 151.84,61.59 152.17,61.92 153.09,61.92 153.44,62.28 153.87,62.28
$20N62170 on TOP (solid shape): 102.26,160.6 102.54,160.6 102.54,161.19 102.77,161.19 102.79,161.16 102.79,160.25 103.39,159.65 103.39,158.94 104.24,158.09 104.24,155.07 104.04,154.86 101.8,154.86 101.68,154.99 101.68,159.61 102.06,159.99 102.06,161.19 102.26,161.19
$20N137118 on TOP (solid shape): 102.68,178.14 102.68,177.81 102.72,177.77 102.72,177.16 103.05,176.83 103.61,176.83 103.61,176.61 102.51,176.61 102.29,176.83 101.75,176.83 101.42,177.16 102.13,177.16 102.13,177.57 101.91,177.57 101.91,177.16 101.42,177.16 101.32,177.27 97.28,177.27 97.21,177.34 97.21,178.64 97.28,178.71 102.11,178.71
$20N181728 on TOP (solid shape): 114.43,177.01 115.04,176.4 115.77,176.4 116.03,176.15 116.03,172.11 115.88,171.96 114.5,171.96 114.1,172.36 114.1,174.65 113.31,175.44 113.31,175.56 114.07,175.56 114.07,175.87 113.64,175.87 113.64,175.56 113.31,175.56 113.31,175.97 113.36,176.02 113.92,176.02 114.1,176.2 114.1,177.29 114.2,177.39 114.2,178.03 114.43,178.03
$20N181730 on TOP (solid shape): 111.23,182.73 111.23,181.05 111.68,180.59 111.68,178.89 111.89,178.69 111.89,178.2 111.89,178.05 112.23,177.71 113.3,177.71 113.61,178.03 113.91,178.03 113.91,177.56 113.54,177.19 112.66,177.19 112.5,177.04 111.51,177.04 111.38,177.17 111.34,177.18 111.32,177.2 111.3,177.22 111.29,177.24 111.3,177.34 112.7,177.34 112.7,177.57 112.19,177.57 112.19,177.34 111.3,177.34 111.3,177.56 111.3,177.63 111.28,177.7 111.26,177.76 111.22,177.83 111.19,177.89 111.14,177.94 111.09,177.99 111.04,178.04 110.98,178.08 110.91,178.11 110.84,178.13 110.77,178.15 110.7,178.16 110.64,178.16 110.29,178.51 110.25,178.52 110.17,178.55 110.08,178.56 110.08,180.19 109.5,180.77 107.8,180.77 107.78,180.84 107.74,180.9 107.71,180.96 107.66,181.02 107.61,181.07 107.56,181.11 107.5,181.15 107.43,181.18 107.36,181.2 107.29,181.22 107.22,181.23 107.15,181.23 107.08,181.22 107.01,181.2 106.94,181.18 106.87,181.15 106.81,181.11 106.76,181.06 106.71,181.01 106.67,180.97 106.65,180.95 106.62,180.94 106.6,180.94 106.57,180.95 106.54,180.96 106.53,180.97 106.02,181.48 106.02,183.31 106.05,183.34 110.62,183.34
$20N212013 on TOP (solid shape): 107.7,33.91 107.7,32.26 107.57,32.13 106.5,32.13 106.3,32.33 106.3,32.41 107.34,32.41 107.34,32.77 107.04,32.77 107.04,32.41 106.3,32.41 106.3,33.91 106.55,34.16 107.44,34.16
$20N212013 on TOP (solid shape): 153.67,58.7 153.67,55.7 152.83,54.86 149.89,54.86 149.76,54.99 149.76,55.14 150.5,55.14 150.5,55.4 150.06,55.4 150.06,55.14 149.76,55.14 149.76,55.42 150.37,56.03 150.37,58.65 150.67,58.95 153.42,58.95
$20N212013 on ART03 (solid shape): outline of 797 points within 106.05,31.88 153.11,55.98
$49N2995 on TOP: 187.63,160.2 187.25,159.82 187.25,157.66 188.01,156.9 190.75,156.9 190.91,157.05 190.91,157.71 190.5,158.11 189.87,158.11 189.46,158.52 189.46,160.1 189.36,160.2 ; 2 cut-outs
$49N44760 on TOP (solid shape): 230.89,196.9 230.89,193.14 230.78,193.04 229.54,193.04 229.26,193.32 229.26,196.9 229.44,197.08 230.71,197.08
$49N191454 on TOP (solid shape): 93.83,167.64 93.83,166.34 93.73,166.24 93.73,166.12 93.47,165.86 93.47,164.72 93.85,164.34 93.85,164.08 93.47,164.08 93.47,163.7 93.73,163.7 93.73,161.67 93.6,161.54 93.09,161.54 92.96,161.67 92.96,163.58 92.71,163.83 92.71,166.11 92.78,166.12 92.84,166.14 92.89,166.16 92.93,166.19 92.98,166.22 93.01,166.26 93.04,166.31 93.07,166.36 93.08,166.41 93.09,166.47 93.09,166.53 93.08,166.59 93.07,166.62 93.09,166.64 93.09,166.98 93.73,166.98 93.73,167.59 93.5,167.59 93.5,166.98 93.09,166.98 93.09,167.13 93.12,167.13 93.12,167.41 93.37,167.66 93.8,167.66
$55N9368 on TOP (solid shape): 101.65,149.68 101.65,149.2 101.91,148.95 103.81,148.95 103.94,148.82 103.94,147.7 101.73,147.7 101.73,148.08 101.47,148.34 100.91,148.34 100.84,148.41 100.84,149.61 100.72,149.72 100.44,149.72 100.43,149.73 99.82,149.73 99.8,149.76 99.8,149.91 99.82,149.94 101.4,149.94
$59N2622 on ART03 (solid shape): 152.55,176.78 152.55,175.79 152.43,175.67 140.74,175.67 140.56,175.84 140.56,176.5 141.1,177.04 152.3,177.04
$59N2622 on ART04 (solid shape): 152.02,176.91 152.02,175.89 151.77,175.64 140.84,175.64 140.72,175.77 140.72,176.28 141.48,177.04 151.89,177.04
$59N15275 on ART03 (solid shape): 182.37,176.15 182.37,175.51 182.12,175.26 172.09,175.26 171.7,175.64 171.7,176.15 171.96,176.4 182.12,176.4
$59N16235 on ART03 (solid shape): 167.64,176.53 167.64,175.89 167.51,175.77 157.86,175.77 157.73,175.89 157.73,176.66 157.86,176.78 167.39,176.78
$59N71921 on TOP (solid shape): 145.49,194.84 145.49,193.47 145.01,192.99 141.22,192.99 140.94,193.27 140.94,194.54 141.25,194.84 143.56,194.84 143.74,195.02 145.31,195.02
$59N72965 on TOP (solid shape): 162.13,195.22 163.58,195.22 163.8,195 163.8,193.22 163.5,192.91 162.56,192.91 162.36,193.12 162.36,193.83 161.8,194.39 160.55,194.39 160.4,194.54 160.4,195.2 160.73,195.53 161.82,195.53
$59N73577 on TOP (solid shape): 170.76,195 170.76,193.14 170.68,193.05 170.32,193.05 169.82,192.56 169.82,191.29 169.67,191.13 168.99,191.13 168.78,191.34 168.78,192.79 169.39,193.4 169.39,195 169.44,195.05 170.71,195.05
$59N73961 on TOP (solid shape): 208.66,196.34 208.66,194.31 208.53,194.18 205.87,194.18 205.61,194.44 205.61,196.6 205.74,196.72 208.28,196.72
$60N1223 on TOP: 217.04,23.49 217.68,23.49 217.81,23.37 217.81,22.48 218.19,22.1 218.19,21.51 218.14,21.46 217.42,21.46 217.37,21.41 217.04,21.41 216.99,21.46 214,21.46 213.72,21.74 213.72,22.28 213.79,22.35 216.66,22.35 216.92,22.61 216.92,23.37 ; 2 cut-outs
$60N1225 on TOP (solid shape): 179.83,28.93 179.83,27.56 179.68,27.41 179.22,27.41 179.12,27.51 179.12,27.74 179.68,27.74 179.68,28.14 179.38,28.14 179.38,27.74 179.12,27.74 179.12,28.3 179.65,28.3 179.65,28.7 179.38,28.7 179.38,28.3 179.12,28.3 179.12,28.9 179.22,29.01 179.76,29.01
$60N1226 on TOP (solid shape): 181.68,33.58 181.68,31.8 181.66,31.8 181.6,31.78 181.55,31.76 181.5,31.74 181.45,31.7 181.41,31.66 181.38,31.61 181.36,31.56 181.34,31.5 181.33,31.45 181.34,31.35 181.23,31.24 181.23,29.72 180.98,29.46 179.45,29.46 179.43,29.49 179.43,30.07 179.45,30.1 179.71,30.1 180.59,30.99 180.59,33.02 181.36,33.02 181.36,33.43 180.98,33.43 180.98,33.02 180.59,33.02 180.59,33.65 180.65,33.71 181.56,33.71
$60N1227 on TOP: 213.87,27.81 217.3,27.81 217.81,27.3 217.81,23.88 217.68,23.75 216.92,23.75 216.54,23.37 216.54,23.11 216.28,22.86 214.43,22.86 214.35,22.78 213.79,22.78 213.74,22.83 213.74,27.69 ; 1 cut-out
$60N1228 on TOP (solid shape): 186.82,33.4 186.82,32 186.31,31.5 184.15,31.5 183.26,30.61 183.26,29.72 183.13,29.59 181.74,29.59 181.48,29.84 181.48,31.04 181.53,31.08 181.56,31.07 181.62,31.05 181.68,31.04 181.74,31.04 181.79,31.05 181.85,31.06 181.9,31.08 181.94,31.11 181.98,31.15 182.02,31.19 182.05,31.24 182.07,31.29 182.09,31.34 182.09,31.39 182.09,31.45 182.08,31.51 182.06,31.57 182.05,31.6 182.07,31.62 182.07,33.04 182.75,33.04 182.75,33.43 182.37,33.43 182.37,33.04 182.07,33.04 182.07,33.53 182.25,33.71 186.51,33.71
$61N11152 on TOP (solid shape): outline of 109 points within 177.83,57.33 189.1,62.46
$63N1357 on TOP (solid shape): 20.32,190.19 20.32,187.93 19.94,187.55 15.24,187.55 14.91,187.88 14.91,189.59 15.02,189.75 15.08,189.94 16.92,189.94 17.65,190.68 19.84,190.68
$63N1358 on TOP: 19.94,185.34 21.08,185.34 21.29,185.14 21.29,183.84 21.23,183.79 16.48,183.79 16.38,183.9 16.38,184.86 16.54,185.01 19.61,185.01
$63N1364 on TOP (solid shape): 28.7,172.97 28.7,170.94 29.21,170.43 29.34,170.43 29.46,170.56 29.46,170.87 29.92,170.87 29.92,171.27 29.72,171.27 29.72,170.87 29.46,170.87 29.46,171.86 29.92,171.86 29.92,172.21 29.67,172.21 29.67,171.86 29.46,171.86 29.46,172.34 29.64,172.52 30,172.52 30.09,172.43 30.09,170.83 30.12,170.79 30.12,170.51 30.56,170.08 30.56,169.32 30.45,169.21 29.54,169.21 28.32,170.43 28.32,172.97 28.35,173 28.68,173
$63N6234 on TOP (solid shape): 6.43,141.17 6.43,140.44 6.68,140.18 9.12,140.18 9.25,140.06 9.25,139.57 9.07,139.39 8.03,139.39 7.82,139.19 7.82,138.28 7.77,138.23 6.05,138.23 5.82,138.45 7.59,138.45 7.59,138.84 7.14,138.84 7.14,138.45 5.82,138.45 5.66,138.61 5.66,139.42 7.34,139.42 7.34,139.93 7.01,139.93 7.01,139.42 5.66,139.42 5.66,141.3 6.3,141.3
$65N2032 on TOP (solid shape): 45.85,7.75 46.48,7.75 46.48,6.22 45.21,6.22 44.27,7.16 42.7,7.16 42.44,7.42 43.59,7.42 43.59,7.85 43.36,7.85 43.36,7.42 42.44,7.42 42.32,7.54 42.32,9.5 42.6,9.78 43.82,9.78
$65N6291 on TOP (solid shape): 23.62,19.94 23.62,17.65 23.5,17.53 20.45,17.53 20.19,17.78 20.19,19.56 20.83,20.19 23.37,20.19
$65N6291 on BOTTOM (solid shape): 20.7,18.92 20.7,17.53 19.81,16.64 16.89,16.64 16.64,16.89 16.64,18.29 17.02,18.67 19.81,18.67 20.19,19.05 20.57,19.05
$65N14401 on TOP (solid shape): 55.68,7.72 56.49,7.72 56.49,6.2 55.22,6.2 54.51,6.91 52.45,6.91 52.17,7.19 53.21,7.19 53.21,7.67 52.93,7.67 52.93,7.19 52.17,7.19 51.89,7.47 51.89,9.07 52.22,9.4 54,9.4
$67N1257 on TOP: 36.58,149.35 38.35,149.35 38.61,149.61 38.61,155.96 38.48,156.08 35.31,156.08 35.31,153.16 34.8,152.65 33.15,152.65 32.33,151.84 32.33,151.31 32.54,151.1 33.5,151.1 33.78,151.38 33.78,151.64 33.91,151.76 36.2,151.76 36.45,151.51 36.45,149.48 ; 1 cut-out
$67N25227 on TOP: 28.12,133.83 29.08,133.83 29.21,133.96 29.21,135.38 29.08,135.51 28.12,135.51 27.99,135.38 27.99,133.96 ; 1 cut-out
$67N25228 on TOP (solid shape): 30.25,137.44 30.25,136.65 30.66,136.25 30.66,135.43 29.64,135.43 29.39,135.69 28.42,135.69 28.28,135.83 28.28,135.91 29.11,135.91 29.11,136.17 28.7,136.17 28.7,135.91 28.28,135.91 28.28,136.25 28.54,136.5 28.54,136.88 29.39,136.88 29.39,137.16 28.85,137.16 28.85,136.88 28.54,136.88 28.54,137.2 28.85,137.52 30.18,137.52
$67N25230 on TOP (solid shape): 32.99,141.2 32.99,136.99 33.25,136.74 33.25,135.86 32.74,135.36 31.22,135.36 31.06,135.51 31.06,136.74 30.91,136.89 30.91,137.9 30.56,138.25 29.28,138.25 29.27,138.29 29.25,138.35 29.21,138.43 29.21,138.79 28.85,138.79 28.85,139.24 28.45,139.24 28.45,138.89 28.38,138.88 28.31,138.88 28.23,138.9 28.19,138.98 28.19,139.29 28.19,141.05 28.58,141.43 32.77,141.43

Small or netless copper shapes (teardrops, artwork), in the pictures only: 8 on TOP, 16 on BOTTOM, 7 on ART03, 1 on ART04

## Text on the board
User.Comments: CR_UNNAMED_6 | CR_UNNAMED_1 | CR_UNNAMED_5 | CR_UNNAMED_3 | CR_SIM_1 | CR_UNNAMED_9 | CR_UNNAMED_8 | CR_UNNAMED_10 | CR_1_21
DIMENSION: 11 | 12 | 14 | 13A4 | 13A1 | 13A5 | 13A3 | 13A2 | 13A6 | 13A10 | 13B2 | 13A12 | 13B1 | 13A9 | 13A13 | 13B5 | 13A8 | 13B4 | 13A7 | 13A11 | 13B3 | 5 | 13A17 | 13B7 | 13A16 | 13A14 | 13A15 | 13B6 | 16 | 4 | TOP
DISPLAY_BOTTOM: LAYER# | 1 | 3 | 4 | 6 | WIDTH/SPACE | 4.99/10.01 | 5.98/9.02 | 6.1/8.9 | 7.4/7.6 | WIDTH | [mil] | 8 | 7 | IMPEDANCE | [ohm] | 100 | 50 | 90 | PRECISION | [+/-%] | 10 | REF LAYER | 2&5 | 5&2 | 2 | 5 | WIDTH TOLERANCE | [dB/inch@xxGHz] | INSERTION LOSS | REMARK | INSERTION LOSS TOLERANCE | DIFFERENTIAL IMPEDANCE LIST | SINGLE IMPEDANCE LIST
PLACE_BOUND_TOP: $21
User.15: FIGURE | SIZE | 8.0 | 10.0 | 12.0 | 14.0 | 28.0 | 34.0 | 36.0 | 42.0 | 52.0 | 55.0 | 59.0 | 72.0 | 76.0 | 98.0 | 138.0 | 168.0 | 189.0 | 197.0 | 205.0 | 40.0 | 43.0 | 45.0 | 49.0 | 53.0 | 63.0 | 65.0 | 78.0 | 79.0 | 100.0 | 102.0 | 106.0 | 110.0 | 118.0 | 125.0 | 130.0 | 177.0 | 55.0x31.0 | 64.0x40.0 | 67.0x32.0 | 85.0x30.0 | 98.0x32.0 | 106.0x31.0 | DRILL CHART: TOP to BOTTOM | ALL UNITS ARE IN MILS | PLATED | NON-PLATED | QTY | 4335 | 4 | 2 | 36 | 18 | 9 | 72 | 6 | 14 | 10 | 12 | 15 | 1 | 3
